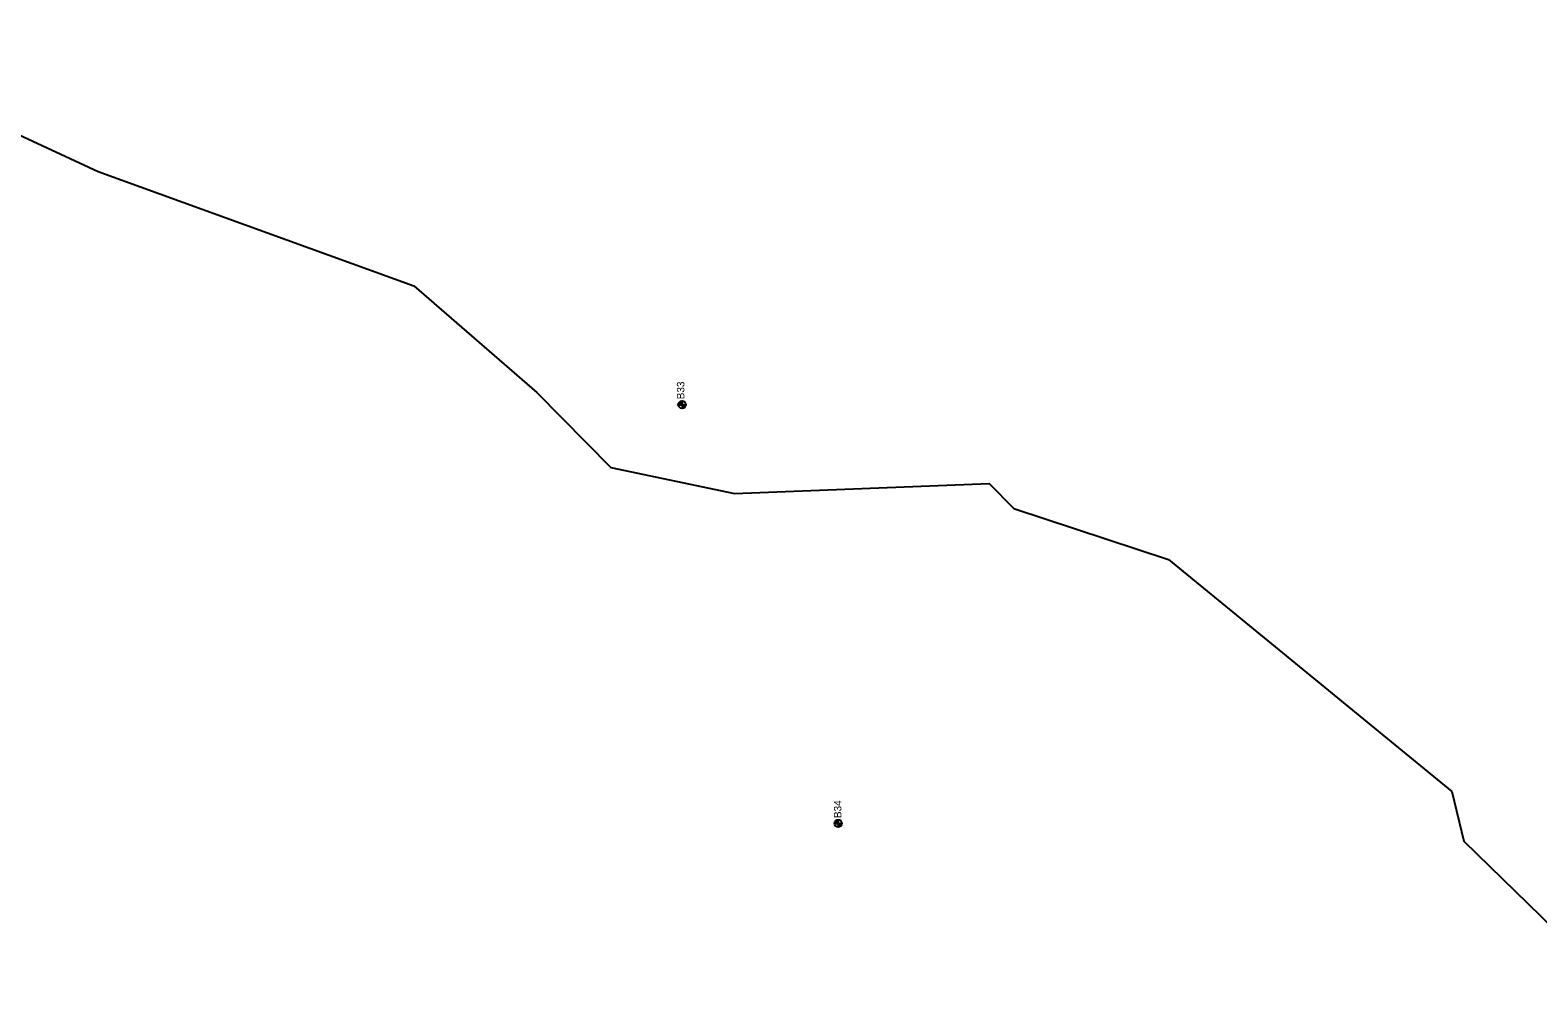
# Model space of a CAD drawing. Extents: x 331323 to 388339, y 121519 to 205315.
# Drawn here: x 360580 to 362606, y 146683 to 147957 of the extents above; entities that cross this region are included whole.
import ezdxf

# ---------------------------------------------------------------- set-up
doc = ezdxf.new("R2010")
doc.units = 0
for name, color, linetype in [('E_SOIL_BORE1 [KAPUR_CADDS_LEVELS]', 7, 'Continuous'), ('Level 57', 7, 'Continuous'), ('P_MARK', 7, 'Continuous')]:
    doc.layers.add(name, color=color, linetype=linetype)

msp = doc.modelspace()

# ---------------------------------------------------------------- linework, layer by layer
at = {"layer": 'Level 57'}
msp.add_lwpolyline([(358783.7, 149243), (359424.1, 149053.9), (359473.8, 149011.8), (359473.5, 148978.4), (359564.1, 148860.9), (359629.6, 148727), (359711.8, 148592.9), (359927, 148416), (360101, 148297.7), (360183.2, 148163.6), (360232, 148029.9), (360414.2, 147886.5), (360671.6, 147767.5), (361095.5, 147613.7), (361261, 147470.5), (361360.1, 147369.6), (361526.6, 147334.8), (361868.7, 147348.4), (361901.7, 147314.7), (362109.6, 147246.2), (362490.3, 146934.4), (362506.4, 146867.6), (362696.5, 146682.5)], dxfattribs=at)
at = {"layer": 'P_MARK'}
for p, q in [((361451, 147454.1), (361461, 147454.1)), ((361456, 147459.1), (361456, 147449.1)), ((361660.8, 146891.4), (361670.8, 146891.4)), ((361665.8, 146896.4), (361665.8, 146886.4))]:
    msp.add_line(p, q, dxfattribs=at)
for centre in [(361456, 147454.1), (361665.8, 146891.4)]:
    msp.add_circle(centre, 5, dxfattribs=at)
for centre, radius, start, end in [((361456, 147454.1), 4.5, 89.9869, 179.9869), ((361456, 147454.1), 4, 89.9869, 179.9869), ((361456, 147454.1), 3.5, 89.9869, 179.9869), ((361456, 147454.1), 3, 89.9869, 179.9869), ((361456, 147454.1), 2.5, 89.9869, 179.9869), ((361456, 147454.1), 2, 89.9869, 179.9869), ((361456, 147454.1), 1.5, 89.9869, 179.9869), ((361456, 147454.1), 1, 89.9869, 179.9869), ((361456, 147454.1), 0.5, 89.9869, 179.9869), ((361456, 147454.1), 4.5, 269.9869, 359.9869), ((361456, 147454.1), 4, 269.9869, 359.9869), ((361456, 147454.1), 3.5, 269.9869, 359.9869), ((361456, 147454.1), 3, 269.9869, 359.9869), ((361456, 147454.1), 2.5, 269.9869, 359.9869), ((361456, 147454.1), 2, 269.9869, 359.9869), ((361456, 147454.1), 1.5, 269.9869, 359.9869), ((361456, 147454.1), 1, 269.9869, 359.9869), ((361456, 147454.1), 0.5, 269.9869, 359.9869), ((361665.8, 146891.4), 4.5, 89.9869, 179.9869), ((361665.8, 146891.4), 4, 89.9869, 179.9869), ((361665.8, 146891.4), 3.5, 89.9869, 179.9869), ((361665.8, 146891.4), 3, 89.9869, 179.9869), ((361665.8, 146891.4), 2.5, 89.9869, 179.9869), ((361665.8, 146891.4), 2, 89.9869, 179.9869), ((361665.8, 146891.4), 1.5, 89.9869, 179.9869), ((361665.8, 146891.4), 1, 89.9869, 179.9869), ((361665.8, 146891.4), 0.5, 89.9869, 179.9869), ((361665.8, 146891.4), 4.5, 269.9869, 359.9869), ((361665.8, 146891.4), 4, 269.9869, 359.9869), ((361665.8, 146891.4), 3.5, 269.9869, 359.9869), ((361665.8, 146891.4), 3, 269.9869, 359.9869), ((361665.8, 146891.4), 2.5, 269.9869, 359.9869), ((361665.8, 146891.4), 2, 269.9869, 359.9869), ((361665.8, 146891.4), 1.5, 269.9869, 359.9869), ((361665.8, 146891.4), 1, 269.9869, 359.9869), ((361665.8, 146891.4), 0.5, 269.9869, 359.9869)]:
    msp.add_arc(centre, radius, start, end, dxfattribs=at)

# ---------------------------------------------------------------- texts
at = {"layer": 'E_SOIL_BORE1 [KAPUR_CADDS_LEVELS]'}
for s, p in [('B33', (361459.1, 147461.4)), ('B34', (361670.1, 146898.6))]:
    msp.add_text(s, height=10, rotation=89.9869, dxfattribs=at).set_placement(p)

doc.saveas('drawing.dxf')
